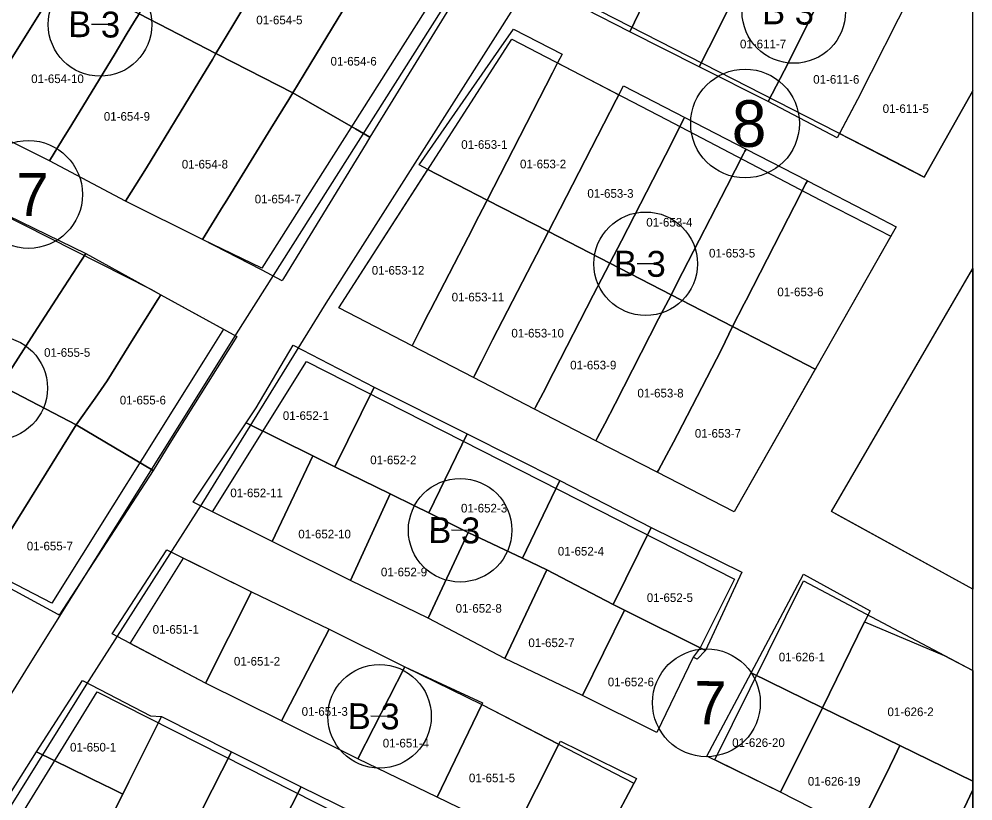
# Model space of a CAD drawing. Extents: x 413946 to 415528, y 4453939 to 4454944.
# Drawn here: x 415383.6 to 415494.2, y 4454164.9 to 4454255.5 of the extents above; entities that cross this region are included whole.
import ezdxf

# ---------------------------------------------------------------- set-up
doc = ezdxf.new("R2010")
doc.units = 0
for name, color, linetype in [('0_KADASTRO', 7, 'Continuous'), ('0_ÇERÇEVE', 7, 'Continuous'), ('Level 27', 7, 'Continuous'), ('Level 28', 7, 'Continuous'), ('Level 29', 7, 'Continuous'), ('Level 32', 7, 'Continuous'), ('Level 58', 7, 'Continuous'), ('Level 62', 7, 'Continuous')]:
    doc.layers.add(name, color=color, linetype=linetype)

msp = doc.modelspace()

# ---------------------------------------------------------------- linework, layer by layer
at = {"layer": '0_KADASTRO'}
for points in [[(415444.13, 4454259.31), (415455.54, 4454276.7), (415464.08, 4454273.33), (415462.22, 4454269.66), (415456.53, 4454258.46), (415454.41, 4454254.02)], [(415397.51, 4454256.08), (415399.7, 4454259.72), (415404.84, 4454268.25), (415406.35, 4454270.75), (415407.28, 4454272.3), (415407.75, 4454273.08), (415416.58, 4454268.39), (415415.75, 4454267.02), (415414.93, 4454265.64), (415408.38, 4454254.73), (415406.43, 4454251.5), (415402.07, 4454253.74)], [(415454.41, 4454254.02), (415456.53, 4454258.46), (415462.22, 4454269.66), (415464.08, 4454273.33), (415472.32, 4454269.69), (415470.24, 4454265.52), (415470.03, 4454265.09), (415464.68, 4454254.37), (415462.44, 4454249.97)], [(415462.44, 4454249.97), (415464.68, 4454254.37), (415470.03, 4454265.09), (415470.24, 4454265.52), (415472.32, 4454269.69), (415480.52, 4454266.08), (415478.92, 4454262.78), (415478.03, 4454260.99), (415472.74, 4454250.36), (415470.45, 4454245.92)], [(415406.43, 4454251.5), (415408.38, 4454254.73), (415414.93, 4454265.64), (415415.75, 4454267.02), (415416.58, 4454268.39), (415425.39, 4454263.7), (415424.63, 4454262.44), (415423.54, 4454260.52), (415422.88, 4454259.36), (415422.35, 4454258.48), (415417.41, 4454250.37), (415416.64, 4454249.1), (415415.33, 4454246.94), (415406.64, 4454251.39)], [(415369.35, 4454248.24), (415369.62, 4454248.68), (415370.4, 4454249.95), (415371.97, 4454252.52), (415374.57, 4454256.75), (415377.92, 4454262.28), (415379.76, 4454265.32), (415388.64, 4454260.63), (415386.5, 4454257.02), (415386.07, 4454256.27), (415380.72, 4454247.74), (415378.51, 4454244.11), (415378.16, 4454243.54), (415373.24, 4454246.17)], [(415470.45, 4454245.92), (415472.74, 4454250.36), (415478.03, 4454260.99), (415478.92, 4454262.78), (415480.52, 4454266.08), (415489.12, 4454262.68), (415487.81, 4454260.05), (415487.09, 4454258.66), (415480.78, 4454246.17), (415478.43, 4454241.74)], [(415415.33, 4454246.94), (415416.64, 4454249.1), (415417.41, 4454250.37), (415422.35, 4454258.48), (415422.88, 4454259.36), (415423.54, 4454260.52), (415424.63, 4454262.44), (415425.39, 4454263.7), (415434.68, 4454258.75), (415433.79, 4454257.31), (415424.26, 4454241.79), (415422.6, 4454242.75)], [(415378.16, 4454243.54), (415378.51, 4454244.11), (415380.72, 4454247.74), (415386.07, 4454256.27), (415386.5, 4454257.02), (415388.64, 4454260.63), (415397.51, 4454256.08), (415396.98, 4454255.23), (415396.01, 4454253.65), (415394.74, 4454251.48), (415389.71, 4454243.28), (415388.64, 4454241.54), (415387.14, 4454239.05)], [(415387.14, 4454239.05), (415388.64, 4454241.54), (415389.71, 4454243.28), (415394.74, 4454251.48), (415396.01, 4454253.65), (415396.98, 4454255.23), (415397.51, 4454256.08), (415402.07, 4454253.74), (415406.43, 4454251.5), (415406.02, 4454250.82), (415404.43, 4454248.2), (415398.39, 4454238.26), (415395.96, 4454234.39)], [(415429.99, 4454238.58), (415439.2, 4454251.88), (415440.9, 4454254.33), (415446.54, 4454251.42), (415446.01, 4454250.4), (415445.42, 4454249.25), (415437.86, 4454234.52), (415431, 4454238.06)], [(415395.96, 4454234.39), (415398.39, 4454238.26), (415404.43, 4454248.2), (415406.02, 4454250.82), (415406.43, 4454251.5), (415406.64, 4454251.39), (415415.33, 4454246.94), (415414.86, 4454246.17), (415412.79, 4454242.81), (415407.48, 4454234.19), (415407.27, 4454233.85), (415404.86, 4454229.93)], [(415437.86, 4454234.52), (415445.42, 4454249.25), (415446.01, 4454250.4), (415453.12, 4454246.72), (415452.81, 4454246.13), (415451.38, 4454243.34), (415446.32, 4454233.48), (415444.97, 4454230.86)], [(415444.97, 4454230.86), (415446.32, 4454233.48), (415451.38, 4454243.34), (415452.81, 4454246.13), (415453.12, 4454246.72), (415453.65, 4454247.76), (415460.76, 4454244.09), (415460.68, 4454243.95), (415460.21, 4454243), (415458.54, 4454239.71), (415453.43, 4454229.78), (415452.08, 4454227.19)], [(415404.86, 4454229.93), (415407.27, 4454233.85), (415407.48, 4454234.19), (415412.79, 4454242.81), (415414.86, 4454246.17), (415415.33, 4454246.94), (415422.6, 4454242.75), (415424.26, 4454241.79), (415423.82, 4454241.08), (415414.26, 4454225.42), (415414.1, 4454225.16), (415411.69, 4454226.41)], [(415452.08, 4454227.19), (415453.43, 4454229.78), (415458.54, 4454239.71), (415460.21, 4454243), (415460.68, 4454243.95), (415460.76, 4454244.09), (415467.87, 4454240.42), (415467.74, 4454240.17), (415467.59, 4454239.88), (415465.65, 4454236.08), (415460.52, 4454226.11), (415459.19, 4454223.52)], [(415459.19, 4454223.52), (415460.52, 4454226.11), (415465.65, 4454236.08), (415467.59, 4454239.88), (415467.74, 4454240.17), (415467.87, 4454240.42), (415474.96, 4454236.77), (415474.98, 4454236.76), (415474.82, 4454236.44), (415473.46, 4454233.75), (415472.77, 4454232.41), (415467.9, 4454222.92), (415467.67, 4454222.47), (415466.3, 4454219.86)], [(415420.66, 4454222.02), (415431, 4454238.06), (415437.86, 4454234.52), (415437.8, 4454234.33), (415436.44, 4454231.75), (415436.19, 4454231.26), (415431.31, 4454221.79), (415431.08, 4454221.35), (415430.07, 4454219.38), (415429.16, 4454217.63)], [(415466.3, 4454219.86), (415467.67, 4454222.47), (415467.9, 4454222.92), (415472.77, 4454232.41), (415473.46, 4454233.75), (415474.82, 4454236.44), (415474.98, 4454236.76), (415482.76, 4454232.73), (415485.28, 4454231.43), (415475.97, 4454215.04), (415475.9, 4454214.91), (415473.86, 4454215.96), (415466.39, 4454219.81)], [(415429.16, 4454217.63), (415430.07, 4454219.38), (415431.08, 4454221.35), (415431.31, 4454221.79), (415436.19, 4454231.26), (415436.44, 4454231.75), (415437.8, 4454234.33), (415437.86, 4454234.52), (415444.97, 4454230.86), (415443.58, 4454228.16), (415443.12, 4454227.27), (415438.47, 4454218.32), (415437.19, 4454215.78), (415436.39, 4454214.19), (415436.27, 4454213.96)], [(415372.36, 4454217.64), (415373.77, 4454219.7), (415379.48, 4454228.4), (415382.29, 4454232.74), (415391.34, 4454228.33), (415388.33, 4454223.69), (415385.36, 4454219.09), (415382.89, 4454215.22), (415381.41, 4454213.06)], [(415436.27, 4454213.96), (415436.39, 4454214.19), (415437.19, 4454215.78), (415438.47, 4454218.32), (415443.12, 4454227.27), (415443.58, 4454228.16), (415444.97, 4454230.86), (415452.08, 4454227.19), (415450.62, 4454224.39), (415450.14, 4454223.5), (415445.57, 4454214.52), (415444.35, 4454212.17), (415443.48, 4454210.51), (415443.37, 4454210.3)], [(415381.41, 4454213.06), (415382.89, 4454215.22), (415385.36, 4454219.09), (415388.33, 4454223.69), (415391.34, 4454228.33), (415400.05, 4454223.54), (415399.7, 4454222.98), (415396.84, 4454218.44), (415393.81, 4454213.57), (415392.41, 4454211.56), (415390.24, 4454208.45)], [(415443.37, 4454210.3), (415443.48, 4454210.51), (415444.35, 4454212.17), (415445.57, 4454214.52), (415450.14, 4454223.5), (415450.62, 4454224.39), (415452.08, 4454227.19), (415459.19, 4454223.52), (415459.14, 4454223.43), (415457.71, 4454220.76), (415452.7, 4454210.91), (415451.49, 4454208.57), (415450.67, 4454207), (415450.48, 4454206.63)], [(415390.24, 4454208.45), (415392.41, 4454211.56), (415393.81, 4454213.57), (415396.84, 4454218.44), (415399.7, 4454222.98), (415400.05, 4454223.54), (415408.85, 4454218.7), (415405.51, 4454213.41), (415401.08, 4454206.34), (415399.14, 4454203.19)], [(415450.48, 4454206.63), (415450.67, 4454207), (415451.49, 4454208.57), (415452.7, 4454210.91), (415457.71, 4454220.76), (415459.14, 4454223.43), (415459.19, 4454223.52), (415466.3, 4454219.86), (415465.02, 4454217.19), (415459.91, 4454207.33), (415459.45, 4454206.45), (415458.65, 4454204.95), (415457.73, 4454203.22), (415457.59, 4454202.97)], [(415457.59, 4454202.97), (415457.73, 4454203.22), (415458.65, 4454204.95), (415459.45, 4454206.45), (415459.91, 4454207.33), (415465.02, 4454217.19), (415466.3, 4454219.86), (415466.39, 4454219.81), (415473.86, 4454215.96), (415475.9, 4454214.91), (415466.83, 4454199), (415466.49, 4454198.4)], [(415409.91, 4454208.68), (415411.07, 4454210.43), (415415.38, 4454217.68), (415424.75, 4454212.85), (415420.22, 4454203.6), (415417.65, 4454204.88)], [(415370.66, 4454196.04), (415371.24, 4454197.01), (415373.72, 4454201.08), (415379.52, 4454210.12), (415380.2, 4454211.18), (415381.21, 4454212.75), (415381.41, 4454213.06), (415390.24, 4454208.45), (415388.65, 4454205.9), (415382.27, 4454195.66), (415379.47, 4454191.16)], [(415420.22, 4454203.6), (415424.75, 4454212.85), (415435.53, 4454207.42), (415431.12, 4454198.27), (415429.46, 4454199.08), (415426.64, 4454200.46)], [(415379.47, 4454191.16), (415382.27, 4454195.66), (415388.65, 4454205.9), (415390.24, 4454208.45), (415399.14, 4454203.19), (415388.27, 4454186.41), (415388.27, 4454186.4), (415388.14, 4454186.48)], [(415403.79, 4454199.5), (415409.91, 4454208.68), (415417.65, 4454204.88), (415412.93, 4454194.95)], [(415431.12, 4454198.27), (415435.53, 4454207.42), (415446.28, 4454202.02), (415441.95, 4454193.02), (415435.67, 4454196)], [(415412.93, 4454194.95), (415417.65, 4454204.88), (415420.22, 4454203.6), (415426.64, 4454200.46), (415422.01, 4454190.41)], [(415441.95, 4454193.02), (415446.28, 4454202.02), (415456.89, 4454196.58), (415452.47, 4454187.64), (415444.77, 4454191.65)], [(415422.01, 4454190.41), (415426.64, 4454200.46), (415429.46, 4454199.08), (415431.12, 4454198.27), (415435.67, 4454196), (415431.02, 4454186.08)], [(415431.02, 4454186.08), (415435.67, 4454196), (415441.95, 4454193.02), (415444.77, 4454191.65), (415439.93, 4454181.39)], [(415452.47, 4454187.64), (415456.89, 4454196.58), (415467.38, 4454191.4), (415463.16, 4454182.31), (415453.79, 4454186.99)], [(415394.41, 4454184.24), (415400.72, 4454193.98), (415410.53, 4454189.11), (415405.21, 4454178.52)], [(415439.93, 4454181.39), (415444.77, 4454191.65), (415452.47, 4454187.64), (415453.79, 4454186.99), (415448.9, 4454177.09)], [(415468.46, 4454179.71), (415474.54, 4454191.15), (415482.25, 4454186.9), (415481.6, 4454185.63), (415476.75, 4454175.67)], [(415405.21, 4454178.52), (415410.53, 4454189.11), (415419.54, 4454184.8), (415414.04, 4454174.16)], [(415448.9, 4454177.09), (415453.79, 4454186.99), (415463.16, 4454182.31), (415462.19, 4454181.3), (415461.73, 4454181.54), (415457.54, 4454172.82)], [(415414.04, 4454174.16), (415419.54, 4454184.8), (415428.34, 4454180.41), (415422.88, 4454169.75)], [(415422.88, 4454169.75), (415428.34, 4454180.41), (415437.33, 4454176.25), (415437.23, 4454176.05), (415432.06, 4454165.33)], [(415463.33, 4454170.09), (415468.46, 4454179.71), (415476.75, 4454175.67), (415471.87, 4454165.89)], [(415385.62, 4454170.56), (415390.94, 4454178.85), (415398.85, 4454174.74), (415400.13, 4454174.67), (415396.34, 4454167.11), (415395.62, 4454165.68), (415394.02, 4454166.46), (415393.67, 4454166.63)], [(415432.06, 4454165.33), (415437.23, 4454176.05), (415446.17, 4454171.45), (415440.92, 4454161.04)], [(415471.87, 4454165.89), (415476.75, 4454175.67), (415485.72, 4454171.29), (415485.08, 4454170.01), (415484.53, 4454168.89), (415480.81, 4454161.35)], [(415391.1, 4454156.67), (415395.62, 4454165.68), (415396.34, 4454167.11), (415400.13, 4454174.67), (415408.21, 4454170.57), (415404.85, 4454163.95), (415404.39, 4454163.03), (415399.16, 4454152.71)], [(415440.92, 4454161.04), (415446.17, 4454171.45), (415446.37, 4454171.82), (415455.16, 4454167.48), (415449.48, 4454156.82)], [(415380.27, 4454162.1), (415385.62, 4454170.56), (415393.67, 4454166.63), (415394.02, 4454166.46), (415395.62, 4454165.68), (415391.1, 4454156.67), (415388.66, 4454157.89), (415381.16, 4454161.66)], [(415399.16, 4454152.71), (415404.39, 4454163.03), (415404.85, 4454163.95), (415408.21, 4454170.57), (415416.31, 4454166.51), (415414.14, 4454162.26), (415412.88, 4454159.79), (415408.53, 4454151.28), (415407.76, 4454149.78), (415407.24, 4454148.76)], [(415407.24, 4454148.76), (415407.76, 4454149.78), (415408.53, 4454151.28), (415412.88, 4454159.79), (415414.14, 4454162.26), (415416.31, 4454166.51), (415424.28, 4454162.63), (415422.5, 4454159.05), (415416.48, 4454147), (415416.43, 4454146.9), (415415.37, 4454144.78)]]:
    msp.add_lwpolyline(points, close=True, dxfattribs=at)
for points in [[(415494.17, 4454260.66), (415489.12, 4454262.68), (415487.81, 4454260.05), (415487.09, 4454258.66), (415480.78, 4454246.17), (415478.69, 4454242.23), (415488.54, 4454237.18), (415494.17, 4454247.16)], [(415494.17, 4454247.16), (415494.17, 4454260.66)], [(415494.17, 4454189.41), (415478.68, 4454197.93), (415477.79, 4454198.42), (415494.17, 4454226.58)], [(415494.17, 4454226.58), (415494.17, 4454189.41)], [(415494.16, 4454167.18), (415485.72, 4454171.29), (415476.75, 4454175.67), (415481.6, 4454185.63), (415490.85, 4454181.74), (415494.16, 4454179.99)], [(415494.16, 4454179.99), (415494.16, 4454167.18)], [(415494.16, 4454166.18), (415489.82, 4454157.01), (415480.81, 4454161.35), (415484.53, 4454168.89), (415485.08, 4454170.01), (415485.72, 4454171.29), (415494.16, 4454167.18)], [(415494.16, 4454167.18), (415494.16, 4454166.18)], [(415494.16, 4454154.85), (415489.82, 4454157.01), (415494.16, 4454166.18)], [(415494.16, 4454166.18), (415494.16, 4454154.85)]]:
    msp.add_lwpolyline(points, dxfattribs=at)
at = {"layer": '0_ÇERÇEVE'}
msp.add_lwpolyline([(413945.57, 4454943.96), (415494.14, 4454943.96), (415494.14, 4453939.48), (413945.57, 4453939.48)], close=True, dxfattribs=at)
at = {"layer": 'Level 27'}
for p, q in [((415494.17, 4454247.16), (415488.54, 4454237.18)), ((415477.79, 4454198.42), (415494.01, 4454226.3)), ((415406.02, 4454198.39), (415416.94, 4454215.82)), ((415494.17, 4454189.41), (415477.79, 4454198.42)), ((415396.48, 4454183.14), (415402.65, 4454193.02)), ((415372.28, 4454144.58), (415392.67, 4454177.52))]:
    msp.add_line(p, q, dxfattribs=at)
for points in [[(415411.74, 4454226.63), (415404.86, 4454229.93), (415395.96, 4454234.39), (415387.14, 4454239.05), (415378.16, 4454243.54), (415369.35, 4454248.24), (415360.4, 4454252.69), (415370.8, 4454269.76), (415380.21, 4454285.19)], [(415484.66, 4454230.34), (415475.97, 4454215.04), (415466.49, 4454198.4)], [(415398.89, 4454224.18), (415400.05, 4454223.54), (415407.32, 4454219.54)], [(415466.49, 4454198.4), (415457.59, 4454202.97), (415450.48, 4454206.63), (415443.37, 4454210.3), (415436.27, 4454213.96), (415429.16, 4454217.63), (415420.66, 4454222.02)], [(415462.54, 4454182.62), (415461.73, 4454181.54), (415457.54, 4454172.82), (415448.9, 4454177.09), (415439.93, 4454181.39), (415431.02, 4454186.08), (415422.01, 4454190.41), (415412.93, 4454194.95), (415406.02, 4454198.39)], [(415402.65, 4454193.02), (415410.53, 4454189.11), (415419.54, 4454184.8), (415428.34, 4454180.41), (415437.23, 4454176.05), (415454.88, 4454166.96), (415449.48, 4454156.82), (415440.92, 4454161.04), (415432.06, 4454165.33), (415422.88, 4454169.75), (415414.04, 4454174.16), (415405.21, 4454178.52), (415396.48, 4454183.14)], [(415392.67, 4454177.52), (415404.5, 4454171.52)], [(415404.5, 4454171.52), (415445.11, 4454150.94), (415427.56, 4454117.48)], [(415494.16, 4454154.85), (415489.82, 4454157.01), (415480.81, 4454161.35), (415471.87, 4454165.89), (415464.24, 4454169.64)]]:
    msp.add_lwpolyline(points, dxfattribs=at)
at = {"layer": 'Level 28'}
for p, q in [((415431.66, 4454258.02), (415411.74, 4454226.63)), ((415420.66, 4454222.02), (415440.72, 4454253.15))]:
    msp.add_line(p, q, dxfattribs=at)
at = {"layer": 'Level 29'}
for p, q in [((415355.2, 4454246.27), (415398.89, 4454224.18)), ((415405.06, 4454221.06), (415405.06, 4454221.06)), ((415405.06, 4454221.06), (415405.06, 4454221.06)), ((415407.32, 4454219.54), (415405, 4454215.84)), ((415405, 4454215.84), (415387.4, 4454187.82)), ((415405, 4454215.84), (415405, 4454215.84)), ((415405, 4454215.84), (415405, 4454215.84)), ((415464.24, 4454169.64), (415474.52, 4454190.37))]:
    msp.add_line(p, q, dxfattribs=at)
for points in [[(415485.2, 4454238.89), (415447.56, 4454258.19)], [(415440.72, 4454253.15), (415458.67, 4454243.84), (415476.52, 4454234.51), (415480.13, 4454232.66)], [(415488.54, 4454237.18), (415485.2, 4454238.89)], [(415480.13, 4454232.66), (415484.66, 4454230.34)], [(415494.01, 4454226.3), (415494.17, 4454226.21)], [(415416.94, 4454215.82), (415466.54, 4454190.59), (415462.54, 4454182.62)], [(415387.4, 4454187.82), (415361.01, 4454201.46), (415335.31, 4454214.49)], [(415474.52, 4454190.37), (415494.16, 4454179.99)]]:
    msp.add_lwpolyline(points, dxfattribs=at)
at = {"layer": 'Level 32'}
for p, q in [((415393.99, 4454254.85), (415391.99, 4454254.87)), ((415457.24, 4454227.12), (415455.24, 4454227.14)), ((415435.73, 4454196.24), (415433.73, 4454196.26)), ((415426.39, 4454174.68), (415424.39, 4454174.7))]:
    msp.add_line(p, q, dxfattribs=at)
for centre in [(415473.41, 4454256.36), (415392.99, 4454254.86), (415456.24, 4454227.13), (415380.9, 4454212.73), (415434.73, 4454196.25), (415425.39, 4454174.69)]:
    msp.add_circle(centre, 6, dxfattribs=at)
at = {"layer": 'Level 58'}
for centre, radius in [((415467.76, 4454243.39), 6.3), ((415384.7, 4454235.16), 6.25), ((415463.28, 4454176.26), 6.25)]:
    msp.add_circle(centre, radius, dxfattribs=at)
at = {"layer": 'Level 62'}
for p, q in [((415419.22, 4454222.56), (415444.76, 4454262.8)), ((415434.26, 4454259.22), (415408.77, 4454219.03)), ((415404.81, 4454199.3), (415419.22, 4454222.56)), ((415408.77, 4454219.03), (415404.97, 4454212.96)), ((415404.97, 4454212.96), (415384.84, 4454180.82)), ((415391.39, 4454178.31), (415404.76, 4454199.21)), ((415404.76, 4454199.21), (415404.81, 4454199.3)), ((415384.84, 4454180.82), (415360.29, 4454141.16)), ((415366.46, 4454138.38), (415391.39, 4454178.31))]:
    msp.add_line(p, q, dxfattribs=at)

# ---------------------------------------------------------------- texts
at = {"layer": '0_KADASTRO'}
for s, p in [('01-654-5', (415411.1, 4454254.88)), ('01-611-7', (415467.17, 4454252.1)), ('01-654-6', (415419.71, 4454250.1)), ('01-654-10', (415385.01, 4454248.07)), ('01-611-6', (415475.66, 4454248)), ('01-611-5', (415483.71, 4454244.61)), ('01-654-9', (415393.43, 4454243.71)), ('01-653-1', (415434.86, 4454240.45)), ('01-654-8', (415402.47, 4454238.17)), ('01-653-2', (415441.67, 4454238.19)), ('01-653-3', (415449.48, 4454234.78)), ('01-654-7', (415410.92, 4454234.13)), ('01-653-4', (415456.31, 4454231.44)), ('01-653-5', (415463.58, 4454227.86)), ('01-653-12', (415424.49, 4454225.87)), ('01-653-6', (415471.5, 4454223.37)), ('01-653-11', (415433.75, 4454222.77)), ('01-653-10', (415440.67, 4454218.59)), ('01-655-5', (415386.5, 4454216.35)), ('01-653-9', (415447.49, 4454214.89)), ('01-653-8', (415455.28, 4454211.64)), ('01-655-6', (415395.28, 4454210.83)), ('01-652-1', (415414.18, 4454209.03)), ('01-653-7', (415461.94, 4454206.98)), ('01-652-2', (415424.31, 4454203.9)), ('01-652-11', (415408.09, 4454200.08)), ('01-652-3', (415434.83, 4454198.31)), ('01-652-10', (415415.97, 4454195.31)), ('01-655-7', (415384.5, 4454193.92)), ('01-652-4', (415446.06, 4454193.32)), ('01-652-9', (415425.55, 4454190.91)), ('01-652-5', (415456.37, 4454187.94)), ('01-652-8', (415434.21, 4454186.7)), ('01-651-1', (415399.09, 4454184.26)), ('01-652-7', (415442.64, 4454182.71)), ('01-651-2', (415408.51, 4454180.57)), ('01-626-1', (415471.67, 4454181.06)), ('01-652-6', (415451.85, 4454178.17)), ('01-651-3', (415416.36, 4454174.75)), ('01-626-2', (415484.27, 4454174.71)), ('01-650-1', (415389.51, 4454170.61)), ('01-651-4', (415425.76, 4454171.08)), ('01-626-20', (415466.27, 4454171.14)), ('01-651-5', (415435.75, 4454167.05)), ('01-626-19', (415475.04, 4454166.66))]:
    msp.add_text(s, height=1, dxfattribs=at).set_placement(p)
at = {"layer": 'Level 32'}
for p in [(415469.72, 4454254.9), (415389.29, 4454253.4), (415452.54, 4454225.67), (415431.03, 4454194.78), (415421.69, 4454173.22)]:
    msp.add_text('B 3', height=3, rotation=359.4141, dxfattribs=at).set_placement(p)
at = {"layer": 'Level 58'}
for s, height, p in [('8', 5.4, (415466.2, 4454240.7)), ('7', 5, (415383.25, 4454232.67)), ('7', 5, (415461.84, 4454173.78))]:
    msp.add_text(s, height=height, rotation=359.4141, dxfattribs=at).set_placement(p)

doc.saveas('drawing.dxf')
